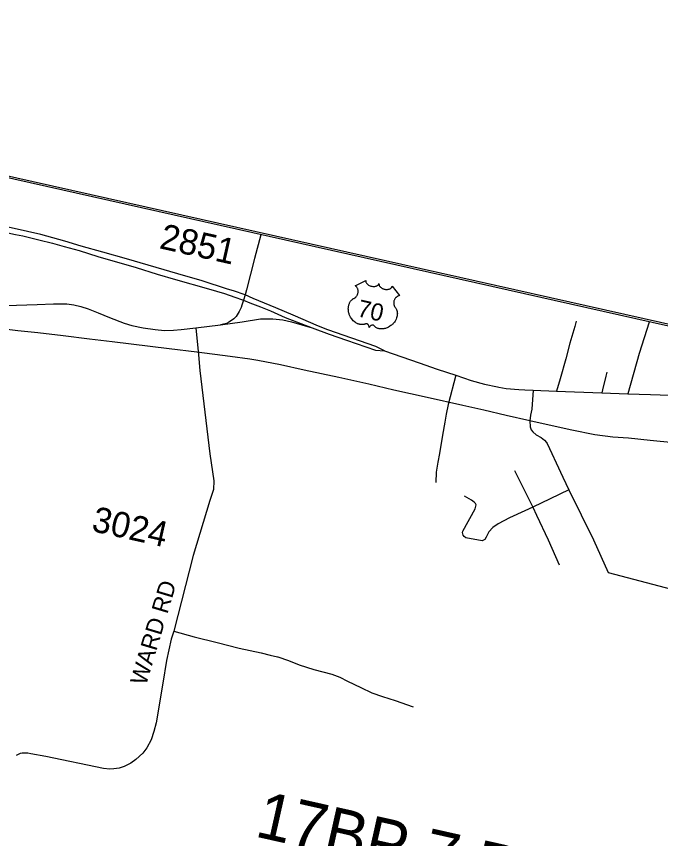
# Model space of a CAD drawing. Extents: x 1784499 to 1786147, y 841097 to 842538.
# Drawn here: x 1784800.3 to 1784969.2, y 842322.5 to 842538 of the extents above; entities that cross this region are included whole.
import ezdxf

# ---------------------------------------------------------------- set-up
doc = ezdxf.new("R2010")
doc.units = 0
for name, color, linetype in [('Exist Railroad Mainline', 7, 'Continuous'), ('Exist Road Primary US Attributed', 7, 'Continuous'), ('Exist Road Primary US Divided Attributed', 7, 'Continuous'), ('Exist Road Primary US Shield Number Label', 7, 'Continuous'), ('Exist Road Secondary Type 51 Attributed', 7, 'Continuous'), ('Exist Road Secondary Type 51 Number Label', 7, 'Continuous'), ('Old_Level_40', 7, 'Continuous'), ('Prop DSN Text', 7, 'Continuous'), ('Scratch_Level_3', 7, 'Continuous')]:
    doc.layers.add(name, color=color, linetype=linetype)

msp = doc.modelspace()

# ---------------------------------------------------------------- linework, layer by layer
at = {"layer": 'Exist Railroad Mainline'}
for points in [[(1784861.5, 842448.13), (1784856.28, 842448.87), (1784847.62, 842449.98), (1784840.29, 842450.84), (1784825.34, 842452.65), (1784819.44, 842453.43), (1784812.51, 842454.23), (1784805.92, 842455.04), (1784800.61, 842455.59), (1784790.82, 842456.82)], [(1784960.81, 842427.46), (1784956.67, 842427.68), (1784951.97, 842428.3), (1784945.95, 842429.55), (1784939.16, 842430.99), (1784934.87, 842431.95), (1784928.67, 842433.38), (1784922.83, 842434.77), (1784917.3, 842435.96), (1784907.95, 842438.1), (1784899.21, 842440.02), (1784892.71, 842441.56), (1784884.86, 842443.32), (1784875.7, 842445.3), (1784869.49, 842446.69), (1784863.59, 842447.76), (1784861.5, 842448.13)], [(1785046.61, 842422.95), (1785045.54, 842422.99), (1785033.4, 842423), (1785027.34, 842423.11), (1785020.23, 842423.39), (1785017.75, 842423.42), (1785006.59, 842423.69), (1784993.72, 842424.19), (1784986.4, 842424.89), (1784981.19, 842425.34), (1784972.67, 842426.19), (1784966.49, 842426.86), (1784960.81, 842427.46)]]:
    msp.add_lwpolyline(points, dxfattribs=at)
at = {"layer": 'Exist Road Primary US Attributed'}
msp.add_line((1784935.77, 842440.04), (1784941.92, 842439.77), dxfattribs=at)
for points in [[(1784896.76, 842450.3), (1784905.84, 842447.22), (1784910.57, 842445.53), (1784915.51, 842443.97)], [(1784915.51, 842443.97), (1784919.55, 842442.52), (1784923.01, 842441.61), (1784926.42, 842440.88), (1784926.74, 842440.77), (1784928.68, 842440.48), (1784931.99, 842440.17), (1784933.63, 842440.13), (1784935.77, 842440.04)], [(1784960.56, 842439.07), (1784966.56, 842438.91), (1784971.59, 842438.72), (1784977.3, 842438.46), (1784981.26, 842438.78), (1784984.51, 842439.22), (1784985.56, 842439.4), (1784988.4, 842440.18), (1784995.56, 842442.49)], [(1784941.92, 842439.77), (1784953.81, 842439.35)], [(1784953.81, 842439.35), (1784960.56, 842439.07)]]:
    msp.add_lwpolyline(points, dxfattribs=at)
at = {"layer": 'Exist Road Primary US Divided Attributed'}
for points in [[(1784775.35, 842486.17), (1784781.15, 842484.98), (1784785.25, 842484.09), (1784789.26, 842483.21), (1784800, 842480.8), (1784801.93, 842480.44), (1784806.17, 842479.41), (1784809.78, 842478.53), (1784812.79, 842477.67), (1784816.72, 842476.6), (1784821.64, 842475.07), (1784831.65, 842472.14), (1784837.18, 842470.45), (1784841.98, 842468.99), (1784850.67, 842466.59), (1784854.86, 842465.36), (1784857.58, 842464.42), (1784859.57, 842463.74), (1784859.86, 842463.6)], [(1784860.26, 842465.03), (1784857.18, 842466.02), (1784855.65, 842466.51), (1784848.95, 842468.65), (1784842.56, 842470.49), (1784829.12, 842474.41), (1784822.96, 842476.2), (1784817.28, 842477.8), (1784812.97, 842479.11), (1784806.72, 842480.83), (1784799.68, 842482.42), (1784793.11, 842483.82), (1784777.48, 842487.11)], [(1784896.76, 842450.3), (1784894.48, 842451.45), (1784881.95, 842455.85), (1784879.46, 842456.82), (1784872.83, 842459.68), (1784868.32, 842461.6), (1784862.36, 842464.09), (1784860.26, 842465.03)], [(1784859.86, 842463.6), (1784861.52, 842462.9), (1784864.26, 842461.9), (1784866.91, 842460.83), (1784870.78, 842459.09), (1784877.83, 842456.32)], [(1784877.83, 842456.32), (1784882.25, 842454.67), (1784886.82, 842453.09), (1784894.42, 842450.51), (1784896.76, 842450.3)]]:
    msp.add_lwpolyline(points, dxfattribs=at)
at = {"layer": 'Exist Road Primary US Shield Number Label'}
for p, q in [((1784889.09, 842467.41), (1784891.92, 842468.78)), ((1784891.91, 842468.68), (1784891.9, 842468.56)), ((1784891.9, 842468.56), (1784891.91, 842468.5)), ((1784891.92, 842468.78), (1784891.91, 842468.68)), ((1784891.91, 842468.5), (1784891.94, 842468.37)), ((1784891.94, 842468.37), (1784892, 842468.21)), ((1784889.16, 842467.36), (1784889.09, 842467.41)), ((1784889.27, 842467.28), (1784889.16, 842467.36)), ((1784889.37, 842467.18), (1784889.27, 842467.28)), ((1784889.45, 842467.09), (1784889.37, 842467.18)), ((1784889.54, 842466.99), (1784889.45, 842467.09)), ((1784889.62, 842466.86), (1784889.54, 842466.99)), ((1784889.7, 842466.71), (1784889.62, 842466.86)), ((1784889.77, 842466.54), (1784889.7, 842466.71)), ((1784889.82, 842466.37), (1784889.77, 842466.54)), ((1784889.85, 842466.24), (1784889.82, 842466.37)), ((1784889.88, 842466.06), (1784889.85, 842466.24)), ((1784892, 842468.21), (1784892.1, 842468.05)), ((1784892.1, 842468.05), (1784892.21, 842467.9)), ((1784892.21, 842467.9), (1784892.29, 842467.81)), ((1784892.29, 842467.81), (1784892.44, 842467.69)), ((1784892.44, 842467.69), (1784892.61, 842467.57)), ((1784892.61, 842467.57), (1784892.8, 842467.46)), ((1784892.8, 842467.46), (1784893, 842467.37)), ((1784893, 842467.37), (1784893.23, 842467.29)), ((1784893.23, 842467.29), (1784893.45, 842467.24)), ((1784893.45, 842467.24), (1784893.71, 842467.2)), ((1784893.71, 842467.2), (1784893.99, 842467.19)), ((1784893.99, 842467.19), (1784894.12, 842467.2)), ((1784894.12, 842467.2), (1784894.27, 842467.21)), ((1784894.27, 842467.21), (1784894.42, 842467.24)), ((1784894.42, 842467.24), (1784894.58, 842467.28)), ((1784894.58, 842467.28), (1784894.71, 842467.33)), ((1784894.71, 842467.33), (1784894.81, 842467.38)), ((1784894.81, 842467.38), (1784894.97, 842467.47)), ((1784894.97, 842467.47), (1784895.1, 842467.57)), ((1784895.1, 842467.57), (1784895.16, 842467.64)), ((1784895.16, 842467.64), (1784895.21, 842467.69)), ((1784895.21, 842467.69), (1784895.29, 842467.83)), ((1784895.29, 842467.83), (1784895.32, 842467.89)), ((1784895.32, 842467.89), (1784895.36, 842468.02)), ((1784895.36, 842468.02), (1784895.34, 842467.91)), ((1784895.34, 842467.91), (1784895.34, 842467.83)), ((1784895.34, 842467.83), (1784895.34, 842467.76)), ((1784895.34, 842467.76), (1784895.35, 842467.68)), ((1784895.35, 842467.68), (1784895.38, 842467.57)), ((1784895.38, 842467.57), (1784895.42, 842467.47)), ((1784895.42, 842467.47), (1784895.5, 842467.32)), ((1784895.5, 842467.32), (1784895.55, 842467.24)), ((1784895.55, 842467.24), (1784895.6, 842467.18)), ((1784895.6, 842467.18), (1784895.74, 842467.03)), ((1784895.74, 842467.03), (1784895.91, 842466.89)), ((1784895.91, 842466.89), (1784895.99, 842466.83)), ((1784895.99, 842466.83), (1784896.08, 842466.78)), ((1784896.08, 842466.78), (1784896.19, 842466.71)), ((1784896.19, 842466.71), (1784896.31, 842466.65)), ((1784896.31, 842466.65), (1784896.43, 842466.6)), ((1784896.43, 842466.6), (1784896.56, 842466.56)), ((1784896.56, 842466.56), (1784896.68, 842466.52)), ((1784896.68, 842466.52), (1784896.79, 842466.49)), ((1784896.79, 842466.49), (1784896.92, 842466.46)), ((1784896.92, 842466.46), (1784897.04, 842466.44)), ((1784897.04, 842466.44), (1784897.17, 842466.43)), ((1784897.17, 842466.43), (1784897.31, 842466.42)), ((1784897.31, 842466.42), (1784897.43, 842466.42)), ((1784897.43, 842466.42), (1784897.58, 842466.43)), ((1784897.58, 842466.43), (1784897.72, 842466.45)), ((1784897.72, 842466.45), (1784897.85, 842466.47)), ((1784897.85, 842466.47), (1784898.01, 842466.51)), ((1784898.01, 842466.51), (1784898.15, 842466.56)), ((1784898.15, 842466.56), (1784898.25, 842466.61)), ((1784898.25, 842466.61), (1784898.38, 842466.69)), ((1784898.38, 842466.69), (1784898.5, 842466.78)), ((1784898.5, 842466.78), (1784898.58, 842466.85)), ((1784898.58, 842466.85), (1784898.64, 842466.93)), ((1784898.64, 842466.93), (1784898.7, 842467.01)), ((1784898.7, 842467.01), (1784898.75, 842467.1)), ((1784898.75, 842467.1), (1784898.78, 842467.18)), ((1784898.78, 842467.18), (1784898.79, 842467.25)), ((1784898.79, 842467.25), (1784900.76, 842464.8)), ((1784888.52, 842463.92), (1784888.68, 842464.01)), ((1784888.68, 842464.01), (1784888.82, 842464.08)), ((1784888.82, 842464.08), (1784888.99, 842464.19)), ((1784888.99, 842464.19), (1784889.08, 842464.25)), ((1784889.08, 842464.25), (1784889.19, 842464.35)), ((1784889.19, 842464.35), (1784889.28, 842464.44)), ((1784889.28, 842464.44), (1784889.36, 842464.52)), ((1784889.36, 842464.52), (1784889.46, 842464.64)), ((1784889.46, 842464.64), (1784889.53, 842464.74)), ((1784889.53, 842464.74), (1784889.62, 842464.89)), ((1784889.62, 842464.89), (1784889.68, 842465)), ((1784889.68, 842465), (1784889.74, 842465.14)), ((1784889.74, 842465.14), (1784889.79, 842465.27)), ((1784889.79, 842465.27), (1784889.83, 842465.44)), ((1784889.83, 842465.44), (1784889.86, 842465.58)), ((1784889.86, 842465.58), (1784889.88, 842465.75)), ((1784889.88, 842465.92), (1784889.88, 842466.06)), ((1784889.88, 842465.75), (1784889.88, 842465.92)), ((1784899.6, 842464.09), (1784899.48, 842463.92)), ((1784899.67, 842464.18), (1784899.6, 842464.09)), ((1784899.75, 842464.27), (1784899.67, 842464.18)), ((1784899.83, 842464.35), (1784899.75, 842464.27)), ((1784899.93, 842464.43), (1784899.83, 842464.35)), ((1784900, 842464.49), (1784899.93, 842464.43)), ((1784900.08, 842464.54), (1784900, 842464.49)), ((1784900.17, 842464.59), (1784900.08, 842464.54)), ((1784900.25, 842464.64), (1784900.17, 842464.59)), ((1784900.44, 842464.72), (1784900.25, 842464.64)), ((1784900.56, 842464.76), (1784900.44, 842464.72)), ((1784900.7, 842464.79), (1784900.56, 842464.76)), ((1784900.76, 842464.8), (1784900.7, 842464.79)), ((1784887.32, 842461.82), (1784887.36, 842462.04)), ((1784887.36, 842462.04), (1784887.4, 842462.23)), ((1784887.4, 842462.23), (1784887.44, 842462.39)), ((1784887.44, 842462.39), (1784887.5, 842462.58)), ((1784887.5, 842462.58), (1784887.58, 842462.77)), ((1784887.58, 842462.77), (1784887.65, 842462.93)), ((1784887.65, 842462.93), (1784887.71, 842463.05)), ((1784887.71, 842463.05), (1784887.8, 842463.19)), ((1784887.8, 842463.19), (1784887.9, 842463.34)), ((1784887.9, 842463.34), (1784888.02, 842463.48)), ((1784888.02, 842463.48), (1784888.12, 842463.59)), ((1784888.12, 842463.59), (1784888.25, 842463.71)), ((1784888.25, 842463.71), (1784888.37, 842463.81)), ((1784888.37, 842463.81), (1784888.52, 842463.92)), ((1784899.23, 842463.19), (1784899.21, 842463.08)), ((1784899.21, 842463.08), (1784899.21, 842462.97)), ((1784899.21, 842462.97), (1784899.21, 842462.88)), ((1784899.21, 842462.88), (1784899.21, 842462.76)), ((1784899.21, 842462.76), (1784899.22, 842462.61)), ((1784899.22, 842462.61), (1784899.25, 842462.47)), ((1784899.25, 842463.3), (1784899.23, 842463.19)), ((1784899.27, 842463.4), (1784899.25, 842463.3)), ((1784899.25, 842462.47), (1784899.31, 842462.24)), ((1784899.3, 842463.5), (1784899.27, 842463.4)), ((1784899.38, 842463.71), (1784899.3, 842463.5)), ((1784899.31, 842462.24), (1784899.4, 842461.99)), ((1784899.42, 842463.8), (1784899.38, 842463.71)), ((1784899.4, 842461.99), (1784899.48, 842461.85)), ((1784899.48, 842463.92), (1784899.42, 842463.8)), ((1784899.48, 842461.85), (1784899.55, 842461.73)), ((1784887.3, 842461.46), (1784887.31, 842461.61)), ((1784887.3, 842461.25), (1784887.3, 842461.46)), ((1784887.31, 842461.12), (1784887.3, 842461.25)), ((1784887.31, 842461.61), (1784887.32, 842461.82)), ((1784887.32, 842460.92), (1784887.31, 842461.12)), ((1784887.35, 842460.71), (1784887.32, 842460.92)), ((1784887.39, 842460.48), (1784887.35, 842460.71)), ((1784887.43, 842460.32), (1784887.39, 842460.48)), ((1784887.51, 842460.06), (1784887.43, 842460.32)), ((1784887.56, 842459.89), (1784887.51, 842460.06)), ((1784887.65, 842459.67), (1784887.56, 842459.89)), ((1784899.55, 842461.73), (1784899.67, 842461.57)), ((1784899.67, 842461.57), (1784899.74, 842461.48)), ((1784899.74, 842461.48), (1784899.81, 842461.37)), ((1784899.81, 842461.37), (1784899.92, 842461.16)), ((1784899.92, 842461.16), (1784899.96, 842461.06)), ((1784899.96, 842461.06), (1784900, 842460.96)), ((1784900, 842460.96), (1784900.04, 842460.85)), ((1784900.04, 842460.85), (1784900.07, 842460.74)), ((1784900.07, 842460.74), (1784900.1, 842460.64)), ((1784900.1, 842460.64), (1784900.14, 842460.41)), ((1784900.14, 842459.72), (1784900.11, 842459.49)), ((1784900.14, 842460.41), (1784900.15, 842460.2)), ((1784900.15, 842459.84), (1784900.14, 842459.72)), ((1784900.15, 842460.2), (1784900.16, 842460.09)), ((1784900.16, 842460.09), (1784900.15, 842459.84)), ((1784887.8, 842459.35), (1784887.65, 842459.67)), ((1784887.9, 842459.16), (1784887.8, 842459.35)), ((1784888.08, 842458.88), (1784887.9, 842459.16)), ((1784888.2, 842458.71), (1784888.08, 842458.88)), ((1784888.38, 842458.49), (1784888.2, 842458.71)), ((1784888.61, 842458.23), (1784888.38, 842458.49)), ((1784888.82, 842458.04), (1784888.61, 842458.23)), ((1784888.95, 842457.93), (1784888.82, 842458.04)), ((1784889.15, 842457.78), (1784888.95, 842457.93)), ((1784889.31, 842457.68), (1784889.15, 842457.78)), ((1784889.46, 842457.59), (1784889.31, 842457.68)), ((1784889.61, 842457.51), (1784889.46, 842457.59)), ((1784899.24, 842457.68), (1784899.06, 842457.48)), ((1784899.38, 842457.86), (1784899.24, 842457.68)), ((1784899.55, 842458.11), (1784899.38, 842457.86)), ((1784899.65, 842458.28), (1784899.55, 842458.11)), ((1784899.76, 842458.48), (1784899.65, 842458.28)), ((1784899.85, 842458.65), (1784899.76, 842458.48)), ((1784899.96, 842458.95), (1784899.85, 842458.65)), ((1784900.05, 842459.21), (1784899.96, 842458.95)), ((1784900.11, 842459.49), (1784900.05, 842459.21)), ((1784889.75, 842457.44), (1784889.61, 842457.51)), ((1784889.93, 842457.38), (1784889.75, 842457.44)), ((1784890.07, 842457.33), (1784889.93, 842457.38)), ((1784890.2, 842457.29), (1784890.07, 842457.33)), ((1784890.33, 842457.26), (1784890.2, 842457.29)), ((1784890.46, 842457.24), (1784890.33, 842457.26)), ((1784890.61, 842457.22), (1784890.46, 842457.24)), ((1784890.75, 842457.21), (1784890.61, 842457.22)), ((1784890.9, 842457.2), (1784890.75, 842457.21)), ((1784891.06, 842457.21), (1784890.9, 842457.2)), ((1784891.21, 842457.22), (1784891.06, 842457.21)), ((1784891.33, 842457.24), (1784891.21, 842457.22)), ((1784891.44, 842457.27), (1784891.33, 842457.24)), ((1784891.59, 842457.31), (1784891.44, 842457.27)), ((1784891.72, 842457.35), (1784891.59, 842457.31)), ((1784891.84, 842457.4), (1784891.72, 842457.35)), ((1784891.96, 842457.45), (1784891.84, 842457.4)), ((1784892.05, 842457.45), (1784891.96, 842457.45)), ((1784892.1, 842457.44), (1784892.05, 842457.45)), ((1784892.17, 842457.42), (1784892.1, 842457.44)), ((1784892.26, 842457.38), (1784892.17, 842457.42)), ((1784892.32, 842457.34), (1784892.26, 842457.38)), ((1784892.39, 842457.28), (1784892.32, 842457.34)), ((1784892.47, 842457.2), (1784892.39, 842457.28)), ((1784892.55, 842457.11), (1784892.47, 842457.2)), ((1784892.61, 842457.02), (1784892.55, 842457.11)), ((1784892.67, 842456.9), (1784892.61, 842457.02)), ((1784892.7, 842456.81), (1784892.67, 842456.9)), ((1784892.74, 842456.72), (1784892.7, 842456.81)), ((1784892.76, 842456.61), (1784892.74, 842456.72)), ((1784892.76, 842456.45), (1784892.76, 842456.61)), ((1784892.82, 842456.56), (1784892.76, 842456.45)), ((1784892.86, 842456.64), (1784892.82, 842456.56)), ((1784892.91, 842456.69), (1784892.86, 842456.64)), ((1784893.02, 842456.81), (1784892.91, 842456.69)), ((1784893.08, 842456.85), (1784893.02, 842456.81)), ((1784893.15, 842456.9), (1784893.08, 842456.85)), ((1784893.25, 842456.96), (1784893.15, 842456.9)), ((1784893.33, 842457), (1784893.25, 842456.96)), ((1784893.43, 842457.04), (1784893.33, 842457)), ((1784893.5, 842457.06), (1784893.43, 842457.04)), ((1784893.62, 842457.08), (1784893.5, 842457.06)), ((1784893.74, 842457.07), (1784893.62, 842457.08)), ((1784893.85, 842457.04), (1784893.74, 842457.07)), ((1784893.9, 842457.02), (1784893.85, 842457.04)), ((1784893.97, 842456.95), (1784893.9, 842457.02)), ((1784894.23, 842456.7), (1784893.97, 842456.95)), ((1784894.38, 842456.58), (1784894.23, 842456.7)), ((1784894.54, 842456.47), (1784894.38, 842456.58)), ((1784894.72, 842456.37), (1784894.54, 842456.47)), ((1784894.89, 842456.29), (1784894.72, 842456.37)), ((1784895.06, 842456.22), (1784894.89, 842456.29)), ((1784895.25, 842456.17), (1784895.06, 842456.22)), ((1784895.43, 842456.13), (1784895.25, 842456.17)), ((1784895.57, 842456.1), (1784895.43, 842456.13)), ((1784895.72, 842456.09), (1784895.57, 842456.1)), ((1784895.88, 842456.07), (1784895.72, 842456.09)), ((1784896.01, 842456.07), (1784895.88, 842456.07)), ((1784896.39, 842456.09), (1784896.01, 842456.07)), ((1784896.62, 842456.12), (1784896.39, 842456.09)), ((1784896.8, 842456.16), (1784896.62, 842456.12)), ((1784897.01, 842456.21), (1784896.8, 842456.16)), ((1784897.25, 842456.29), (1784897.01, 842456.21)), ((1784897.51, 842456.39), (1784897.25, 842456.29)), ((1784897.7, 842456.47), (1784897.51, 842456.39)), ((1784897.83, 842456.54), (1784897.7, 842456.47)), ((1784898.06, 842456.67), (1784897.83, 842456.54)), ((1784898.23, 842456.78), (1784898.06, 842456.67)), ((1784898.45, 842456.93), (1784898.23, 842456.78)), ((1784898.64, 842457.08), (1784898.45, 842456.93)), ((1784898.81, 842457.23), (1784898.64, 842457.08)), ((1784898.94, 842457.36), (1784898.81, 842457.23)), ((1784899.06, 842457.48), (1784898.94, 842457.36))]:
    msp.add_line(p, q, dxfattribs=at)
at = {"layer": 'Exist Road Secondary Type 51 Attributed'}
for p, q in [((1784860.26, 842465.03), (1784859.86, 842463.6)), ((1784847.34, 842456.39), (1784853.8, 842457.15))]:
    msp.add_line(p, q, dxfattribs=at)
for points in [[(1784864.39, 842480.77), (1784862.67, 842474.53), (1784860.6, 842466.34), (1784860.26, 842465.03)], [(1784781.14, 842461.65), (1784805.69, 842462.5), (1784809.99, 842462.64), (1784813.5, 842462.65), (1784815.32, 842462.37), (1784817.19, 842461.96), (1784819.12, 842461.32), (1784821.74, 842460.25), (1784824.64, 842459.11), (1784828.56, 842457.57), (1784830.56, 842456.96), (1784833.55, 842456.32), (1784836.66, 842455.88), (1784839.1, 842455.69), (1784841.45, 842455.74), (1784843.49, 842455.89), (1784847.34, 842456.39)], [(1784859.86, 842463.6), (1784859.41, 842462.32), (1784859.18, 842461.65), (1784858.72, 842460.62), (1784858.2, 842459.75), (1784857.88, 842459.35), (1784857.79, 842459.23), (1784857.31, 842458.71), (1784856.42, 842458.07), (1784855.97, 842457.81), (1784855.32, 842457.53), (1784853.8, 842457.15)], [(1784853.8, 842457.15), (1784859.43, 842457.96), (1784864.28, 842458.68), (1784867.54, 842458.75), (1784870.15, 842458.44), (1784872.39, 842457.89), (1784877.83, 842456.32)], [(1784947.03, 842458.09), (1784946.73, 842456.67), (1784945.39, 842452.32), (1784944.33, 842448.22), (1784942.88, 842443.02), (1784941.92, 842439.77)], [(1784966.19, 842457.95), (1784966.15, 842457.83), (1784963.61, 842449.65), (1784960.56, 842439.07)], [(1784847.34, 842456.39), (1784847.99, 842449.28)], [(1784847.99, 842449.28), (1784848.41, 842445.2), (1784850.99, 842423.32), (1784852.01, 842416.26), (1784851.99, 842413.99), (1784851.02, 842411.12), (1784846.64, 842396.65), (1784841.54, 842376.82)], [(1784955.11, 842444.75), (1784954.84, 842443.7), (1784953.91, 842440.09), (1784953.81, 842439.35)], [(1784915.51, 842443.97), (1784913.45, 842436.22), (1784912.99, 842433.73), (1784912.62, 842431.62), (1784912.03, 842428.22), (1784911.22, 842423.4), (1784910.75, 842421.18), (1784910.32, 842418.52), (1784910.21, 842415.79)], [(1784935.77, 842440.04), (1784935.39, 842435.06), (1784935.06, 842433.49), (1784934.87, 842431.95)], [(1784934.87, 842431.95), (1784934.99, 842430.37), (1784935.23, 842429.66), (1784935.66, 842429.1), (1784936.59, 842428.34), (1784937.9, 842427.58), (1784938.71, 842426.93), (1784939.31, 842426.34), (1784939.46, 842426.03), (1784940.68, 842423.44), (1784941.82, 842420.96), (1784943.52, 842417.19), (1784945.13, 842413.87)], [(1784930.85, 842418.97), (1784933.73, 842413.22), (1784935.66, 842409.35)], [(1784945.13, 842413.87), (1784940.25, 842411.51), (1784935.66, 842409.35)], [(1784945.13, 842413.87), (1784951.56, 842400.81), (1784955.43, 842392.21)], [(1784935.66, 842409.35), (1784933.63, 842408.39), (1784929.61, 842406.56), (1784926.58, 842405), (1784925.19, 842404.06), (1784924.13, 842402.93), (1784923.44, 842401.53), (1784923.1, 842400.86), (1784922.41, 842400.52), (1784918.16, 842401.29), (1784917.68, 842401.64), (1784917.39, 842402.02), (1784917.22, 842402.68), (1784917.3, 842403.03), (1784920.55, 842408.9), (1784920.77, 842409.6), (1784920.79, 842409.97), (1784920.62, 842410.32), (1784920.33, 842410.69), (1784919.58, 842411.23), (1784917.74, 842412.2)], [(1784935.66, 842409.35), (1784936.69, 842407.27), (1784939.71, 842400.75), (1784942.55, 842394.26)], [(1784955.43, 842392.21), (1784973.71, 842387.42), (1784976.25, 842386.75)], [(1784841.54, 842376.82), (1784840.84, 842374.72), (1784839.6, 842369.2), (1784838.65, 842363.21), (1784836.9, 842352.86), (1784836.33, 842350.53), (1784835.59, 842348.34), (1784834.44, 842346.29), (1784833.42, 842344.89), (1784831.62, 842343.2), (1784830.24, 842342.22), (1784828.51, 842341.38), (1784827.21, 842340.98), (1784825.84, 842340.77), (1784824.74, 842340.7), (1784823.09, 842340.86), (1784808.02, 842343.96), (1784804.04, 842344.74), (1784803.23, 842344.89), (1784801.82, 842344.84), (1784801.25, 842344.77), (1784800.23, 842344.28)], [(1784841.54, 842376.82), (1784846.85, 842375.35), (1784852.95, 842373.87), (1784858.65, 842372.37), (1784864.45, 842371.18), (1784866.85, 842370.53), (1784868.77, 842370.1), (1784868.81, 842370.09)], [(1784868.81, 842370.09), (1784871.66, 842369.12), (1784874.41, 842368.06), (1784878.22, 842366.77), (1784882.95, 842365.59), (1784885.1, 842364.78), (1784887.09, 842363.78), (1784890.59, 842362.11), (1784893.49, 842360.68), (1784896.27, 842359.73), (1784899.57, 842358.65), (1784904.29, 842357.06)]]:
    msp.add_lwpolyline(points, dxfattribs=at)
at = {"layer": 'Old_Level_40'}
msp.add_line((1784611.59, 842537.98), (1785099.64, 842428.53), dxfattribs=at)
at = {"layer": 'Scratch_Level_3'}
msp.add_lwpolyline([(1785039.41, 842390.83), (1785050.23, 842439.1), (1784611.48, 842537.49), (1784510.23, 842085.98), (1784998.27, 841976.54), (1785088.7, 842379.78)], close=True, dxfattribs=at)

# ---------------------------------------------------------------- texts
at = {"layer": 'Exist Road Primary US Shield Number Label'}
msp.add_text('70', height=4.513, rotation=347.3599, dxfattribs=at).set_placement((1784889.42, 842459.42))
at = {"layer": 'Exist Road Secondary Type 51 Number Label'}
for s, p in [('2851', (1784837.52, 842477.25)), ('3024', (1784819.71, 842403.15))]:
    msp.add_text(s, height=6.665, rotation=347.3599, dxfattribs=at).set_placement(p)
at = {"layer": 'Old_Level_40'}
msp.add_text('17BP.7.R.116', height=12.2195, rotation=347.3599, dxfattribs=at).set_placement((1784862.52, 842323.1))
at = {"layer": 'Prop DSN Text'}
msp.add_text('WARD RD', height=4.397, rotation=73.3546, dxfattribs=at).set_placement((1784834.23, 842362.4))

doc.saveas('drawing.dxf')
